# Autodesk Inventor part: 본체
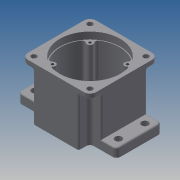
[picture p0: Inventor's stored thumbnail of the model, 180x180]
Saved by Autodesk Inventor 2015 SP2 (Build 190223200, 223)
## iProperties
Created: 2015-06
Part Number: 본체
Material: 알루미늄 6061
Document SubType Name: Modeling
Designer: AMC
Density: 2.7 g/cm^3
Appearance: 기본값
Mass: 702.426 g
Surface Area: 674.008 cm^2
Volume: 260.158 cm^3
Author: AMC
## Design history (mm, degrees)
sketch "스케치1"
  geometry: L1 (-45, -45)-(45, -45); L2 (45, -45)-(45, 45); L3 (45, 45)-(-45, 45); L4 (-45, 45)-(-45, -45); L5 (-45, -45)-(45, 45); L6 (45, -45)-(-45, 45); 1 further point
  constraints: 12 end point, 2 midpoint, 2 parallel, 1 horizontal, 1 perpendicular
  dimensions: "d0" = 90 distance of L2.end L3.end; "d1" = 90 distance of L1.end L2.end (= d0)
extrude "돌출1" new body sketch "스케치1" distance "d2" = 7; taper "d3" = 0 deg
fillet "모깎기1" dims "d4" = 8
sketch "스케치2"
  geometry: L1 (45, 37)-(45, -37) reference; L2 (37, -45)-(-37, -45) reference; L3 (-45, -37)-(-45, 37) reference; L4 (-37, 45)-(37, 45) reference; L5 (30, -45)-(-30, -45); L6 (-30, -45)-(-30, -30); L7 (-30, -30)-(-45, -30); L8 (-45, -30)-(-45, 30); L9 (-45, 30)-(-30, 30); L10 (-30, 30)-(-30, 45); L11 (-30, 45)-(30, 45); L12 (30, 45)-(30, 30); L13 (30, 30)-(45, 30); L14 (45, 30)-(45, -30); L15 (45, -30)-(30, -30); L16 (30, -30)-(30, -45); A1 r 8 centre (37, 37) between (45, 37) and (37, 45) reference; A2 r 8 centre (37, -37) between (37, -45) and (45, -37) reference; A3 r 8 centre (-37, -37) between (-45, -37) and (-37, -45) reference; A4 r 8 centre (-37, 37) between (-37, 45) and (-45, 37) reference; 1 further point
  constraints: 24 end point, 10 perpendicular, 2 point on line, 1 horizontal
  dimensions: "d5" = 15 distance between parallel lines of L1 L16; "d6" = 15 distance between parallel lines of L3 L6 (= d5); "d7" = 15 distance between parallel lines of L1 L12 (= d5); "d8" = 0 distance between parallel lines of L2 L5; "d9" = 0 distance between parallel lines of L4 L11; "d10" = 0 distance between parallel lines of L1 L14; "d11" = 0 distance between parallel lines of L3 L8; "d12" = 15 distance between parallel lines of L4 L13 (= d5); "d13" = 15 distance between parallel lines of L2 L15 (= d5); "d14" = 15 distance between parallel lines of L2 L7 (= d6); "d15" = 15 distance between parallel lines of L4 L9 (= d14)
extrude "돌출2" join sketch "스케치2" distance "d16" = 51; taper "d17" = 0 deg
sketch "스케치3"
  geometry: L1 (45, -30)-(30, -30) reference; L2 (30, -30)-(30, -45) reference; L3 (30, -45)-(-30, -45) reference; L4 (-30, -45)-(-30, -30) reference; L5 (-30, -30)-(-45, -30) reference; L6 (-45, -30)-(-45, 30) reference; L7 (-45, 30)-(-30, 30) reference; L8 (-30, 30)-(-30, 45) reference; L9 (-30, 45)-(30, 45) reference; L10 (30, 45)-(30, 30) reference; L11 (30, 30)-(45, 30) reference; L12 (45, 30)-(45, -30) reference; L13 (30, -45)-(30, -30); L14 (30, -30)-(65, -30); L15 (-30, -45)-(30, -45); L16 (-30, -45)-(-30, -30); L17 (-30, -30)-(-65, -30); L18 (-65, -30)-(-65, 30); L19 (-65, 30)-(-30, 30); L20 (-30, 30)-(-30, 45); L21 (-30, 45)-(30, 45); L22 (-37, 45)-(37, 45) reference; L23 (30, 30)-(30, 45); L24 (30, 30)-(65, 30); L25 (65, 30)-(65, -30); 1 further point
  constraints: 24 end point, 5 perpendicular, 4 collinear, 2 horizontal, 1 point on line
  dimensions: "d18" = 35 distance of L1.end L14.end; "d19" = 35 distance of L4.end L17.end
extrude "돌출3" join sketch "스케치3" distance "d20" = 12; taper "d21" = 0 deg
sketch "스케치4"
  geometry: L1 (30, 45)-(30, 30) reference; L2 (30, 30)-(65, 30) reference; L3 (65, 30)-(65, -30) reference; L4 (65, -30)-(30, -30) reference; L5 (30, -30)-(30, -45) reference; L6 (30, -45)-(-30, -45) reference; L7 (-30, -45)-(-30, -30) reference; L8 (-30, -30)-(-65, -30) reference; L9 (-65, -30)-(-65, 30) reference; L10 (-65, 30)-(-30, 30) reference; L11 (-30, 30)-(-30, 45) reference; L12 (-30, 45)-(30, 45) reference; C1 r 25 at (0, -11); 1 further point
  constraints: 1 centre point, 1 vertical alignment
  dimensions: "d22" = 50 diameter of C1; "d23" = 11 distance of point (0, 0) C1.centre
extrude "돌출4" join sketch "스케치4" distance "d24" = 7; taper "d25" = 0 deg
sketch "스케치5"
  geometry: C1 r 40 at (0, 0); 1 further point
  constraints: 1 centre point, 1 coincident
  dimensions: "d26" = 80 diameter of C1
extrude "돌출5" cut sketch "스케치5" distance "d27" = 9; taper "d28" = 0 deg
sketch "스케치6"
  geometry: C1 r 40 at (0, 0) reference; C2 r 39 at (0, 0); 1 further point
  constraints: 1 centre point, 1 coincident
  dimensions: "d29" = 78 diameter of C2
extrude "돌출6" cut sketch "스케치6" distance "d30" = 52; taper "d31" = 0 deg
sketch "스케치7"
  geometry: A1 r 14 centre (0, 20) between (7.402, 8.117) and (-7.402, 8.117); A2 r 20.5 centre (0, -11) between (-7.402, 8.117) and (7.402, 8.117); 1 further point
  constraints: 4 point on circle, 2 centre point, 2 vertical alignment
  dimensions: "d32" = 41 diameter of A2; "d33" = 28 diameter of A1; "d34" = 20 distance of point (0, 0) A1.centre; "d35" = 11 distance of point (0, 0) A2.centre
extrude "돌출7" join sketch "스케치7" distance "d36" = 7; taper "d37" = 0 deg
sketch "스케치8"
  geometry: L1 (14, -63)-(14, -70) reference; L2 (14, -70)-(-36, -70) reference; L3 (-36, -70)-(-36, -63) reference; L4 (-36, -63)-(-45, -63) reference; L5 (-45, -63)-(-45, 7) reference; L6 (-45, 7)-(-40, 7) reference; L7 (-40, 7)-(-40, -2) reference; L8 (-40, -2)-(-39, -2) reference; L9 (-39, -2)-(-39, -54) reference; L10 (-39, -54)-(-31.5, -54) reference; L11 (-31.5, -54)-(-31.5, -47) reference; L12 (-31.5, -47)-(34, -47) reference; L13 (34, -47)-(34, -54) reference; L14 (34, -54)-(39, -54) reference; L15 (39, -54)-(39, -2) reference; L16 (39, -2)-(40, -2) reference; L17 (40, -2)-(40, 7) reference; L18 (40, 7)-(45, 7) reference; L19 (45, 7)-(45, -63) reference; L20 (45, -63)-(14, -63) reference; L21 (-36, -70)-(14, -70) reference; L22 (-27, -70)-(-27, -62); L23 (-27, -62)-(-23.5, -62); L24 (-30, -63)-(30, -63) reference; L25 (-23.5, -62)-(-23.5, -57); L26 (-23.5, -57)-(-28.5, -57); L27 (-28.5, -57)-(-28.5, -47); L28 (8.117, -47)-(-31.5, -47) reference; L29 (-11, -70)-(-11, -47); 1 further point
  constraints: 12 end point, 5 perpendicular, 3 point on line, 1 midpoint, 1 parallel
  dimensions: "d38" = 32 diameter of L22 L29; "d39" = 8 distance of L22.start L22.end; "d40" = 5 distance of L23.end L25.end; "d41" = 25 diameter of L25 L29; "d42" = 35 diameter of L27 L29
revolve "회전1" sketch "스케치8" stored, may be unused: angle "d43" = 90 deg
sketch "스케치9"
  geometry: C1 r 11 at (0, 20); 1 further point
  constraints: 1 centre point
  dimensions: "d44" = 20 distance of point (0, 0) C1.centre; "d45" = 22 diameter of C1
extrude "돌출8" cut sketch "스케치9" distance "d46" = 7; taper "d47" = 0 deg
sketch "스케치10"
  geometry: L1 (-30, 10)-(-30, 25) reference; L2 (-30, 25)-(30, 25) reference; L3 (30, 25)-(30, 10) reference; L4 (30, 10)-(65, 10) reference; L5 (65, 10)-(65, -50) reference; L6 (65, -50)-(30, -50) reference; L7 (30, -50)-(30, -65) reference; L8 (30, -65)-(-30, -65) reference; L9 (-30, -65)-(-30, -50) reference; L10 (-30, -50)-(-65, -50) reference; L11 (-65, -50)-(-65, 10) reference; L12 (-65, 10)-(-30, 10) reference; C1 r 9.5 at (0, 0); C2 r 11 at (0, 0) reference; C3 r 17.5 at (0, -31) reference; C4 r 39 at (0, -20) reference; A1 r 20.5 centre (0, -31) between (-7.402, -11.883) and (7.402, -11.883) reference; A2 r 14 centre (0, 0) between (7.402, -11.883) and (-7.402, -11.883) reference; 1 further point
  constraints: 1 centre point, 1 coincident
  dimensions: "d48" = 19 diameter of C1
extrude "돌출9" cut sketch "스케치10" distance "d49" = 1; taper "d50" = 0 deg
fillet "모깎기2" dims "d51" = 1, "d52" = 0.3
chamfer "모따기1" distance "d53" = 1; stored, may be unused: second distance "d54" = 2, angle "d55" = 45 deg
sketch "스케치11"
  geometry: L1 (30, 30)-(45, 30) reference; L2 (45, 30)-(45, -30) reference; L3 (45, -30)-(30, -30) reference; L4 (30, -30)-(30, -45) reference; L5 (30, -45)-(-30, -45) reference; L6 (-30, -45)-(-30, -30) reference; L7 (-30, -30)-(-45, -30) reference; L8 (-45, -30)-(-45, 30) reference; L9 (-45, 30)-(-30, 30) reference; L10 (-30, 30)-(-30, 45) reference; L11 (-30, 45)-(30, 45) reference; L12 (30, 45)-(30, 30) reference; L13 (21.763, -27.411)-(24.429, -30.401); L14 (27.411, -21.763)-(30.401, -24.429); L15 (0, 0)-(27.393, 0); C1 r 40 at (0, 0) reference; A1 r 39 centre (0, 0) between (24.429, -30.401) and (30.401, -24.429) reference; A2 r 35 centre (0, 0) between (24.749, -24.749) and (21.763, -27.411); A3 r 4 centre (24.749, -24.749) between (21.763, -27.411) and (27.411, -21.763); 1 further point
  constraints: 7 point on circle, 6 end point, 2 centre point, 1 coincident, 1 equal length, 1 horizontal, 1 tangent, 2 other
  dimensions: "d56" = 70 diameter of A2; "d57" = 8 diameter of A3; "d58" = 45 deg dimension on point (0, 0) A2.start L15.end
extrude "돌출10" join sketch "스케치11" stored distance "d59" = 1; taper "d60" = 0 deg
hole "구멍1" diameter "d63" = 3.459; stored, may be unused: countersink angle "d67" = 82 deg, drill point angle "d69" = 118 deg; dims "d61" = 10, "d62" = 10, "d64" = 12, "d65" = 3.023, "d66" = 2, "d68" = 15
sketch "스케치12"
  geometry: L1 (-45, 30)-(-30, 30) reference; L2 (-30, 30)-(-30, 45) reference; L3 (-30, 45)-(30, 45) reference; L4 (30, 45)-(37, 45) reference; L5 (45, 37)-(45, 30) reference; L6 (30, 30)-(45, 30) reference; L7 (30, 45)-(30, 30) reference; L8 (-45, 30)-(-45, 37) reference; L9 (-45, -30)-(-45, 30) reference; L10 (-30, -30)-(-45, -30) reference; L11 (-30, -45)-(-30, -30) reference; L12 (-30, -45)-(-37, -45) reference; L13 (-45, -37)-(-45, -30) reference; L14 (-37, 45)-(-30, 45) reference; L15 (45, 30)-(45, -30) reference; L16 (45, -30)-(45, -37) reference; L17 (37, -45)-(30, -45) reference; L18 (30, -45)-(-30, -45) reference; L19 (45, -30)-(30, -30) reference; L20 (30, -30)-(30, -45) reference; C1 r 40 at (0, 0) reference; A1 r 8 centre (37, 37) between (45, 37) and (37, 45) reference; A2 r 8 centre (-37, -37) between (-45, -37) and (-37, -45) reference; A3 r 8 centre (-37, 37) between (-37, 45) and (-45, 37) reference; A4 r 8 centre (37, -37) between (37, -45) and (45, -37) reference; 1 further point
hole "구멍2" sketch "스케치12" at (-37, -37), (37, -37), (37, 37), (-37, 37) diameter "d73" = 7; stored, may be unused: countersink angle "d77" = 82 deg, drill point angle "d79" = 118 deg; dims "d74" = 8, "d75" = 3.023, "d76" = 2, "d78" = 10.8
fillet "모깎기3" dims "d80" = 3, "d81" = 5, "d98" = 3.5
fillet "모깎기4" dims "d82" = 2
sketch "스케치13"
  geometry: L1 (-65, 25)-(-65, -25) reference; L2 (-43, 30)-(-60, 30) reference; L3 (-60, -30)-(-43, -30) reference; L4 (43, -30)-(60, -30) reference; L5 (65, -25)-(65, 25) reference; L6 (60, 30)-(43, 30) reference; 5 further points
  dimensions: "d83" = 10 distance from line of L1 point (-55, 17.5); "d84" = 12.5 distance from line of L2 point (-55, 17.5); "d85" = 10 distance from line of L1 point (-55, -17.5) (= d83); "d86" = 12.5 distance from line of L3 point (-55, -17.5) (= d84); "d87" = 12.5 distance from line of L4 point (55, -17.5) (= d86); "d88" = 10 distance from line of L5 point (55, -17.5) (= d83); "d89" = 12.5 distance from line of L6 point (55, 17.5) (= d84); "d90" = 10 distance from line of L5 point (55, 17.5)
hole "구멍3" sketch "스케치13" at (-55, 17.5), (-55, -17.5), (55, -17.5), (55, 17.5) diameter "d91" = 9; stored, may be unused: countersink angle "d95" = 82 deg, drill point angle "d97" = 118 deg; dims "d92" = 8, "d93" = 3.023, "d94" = 2, "d96" = 10.8
sketch "스케치14"
  geometry: L1 (28, 45)-(-28, 45) reference; 2 further points
  constraints: 1 vertical alignment, 1 other
  dimensions: "d99" = 15 distance from line of point (0, 30) L1
feature "엠보싱1" sketch "스케치14" dims "d0" = 90, "d1" = 90 (= d0), "d100" = 0.5, "d101" = 0
node "솔리드1"
pattern_circular "원형 패턴1" dims angle "d71" = 360 deg
node "투영된 루프1"
node "절단 모서리 투영1"
node "절단 모서리 투영2"
node "절단 모서리 투영3"
node "절단 모서리 투영4"
node "절단 모서리 투영5"
node "절단 모서리 투영6"
node "절단 모서리 투영7"
